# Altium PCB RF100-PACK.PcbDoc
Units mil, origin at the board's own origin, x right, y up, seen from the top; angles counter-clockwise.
Board outline 6000 x 4000 mil, 2 copper layers (Top Layer, Bottom Layer); 18 components, 15 nets, 75 pads, 285 vias.
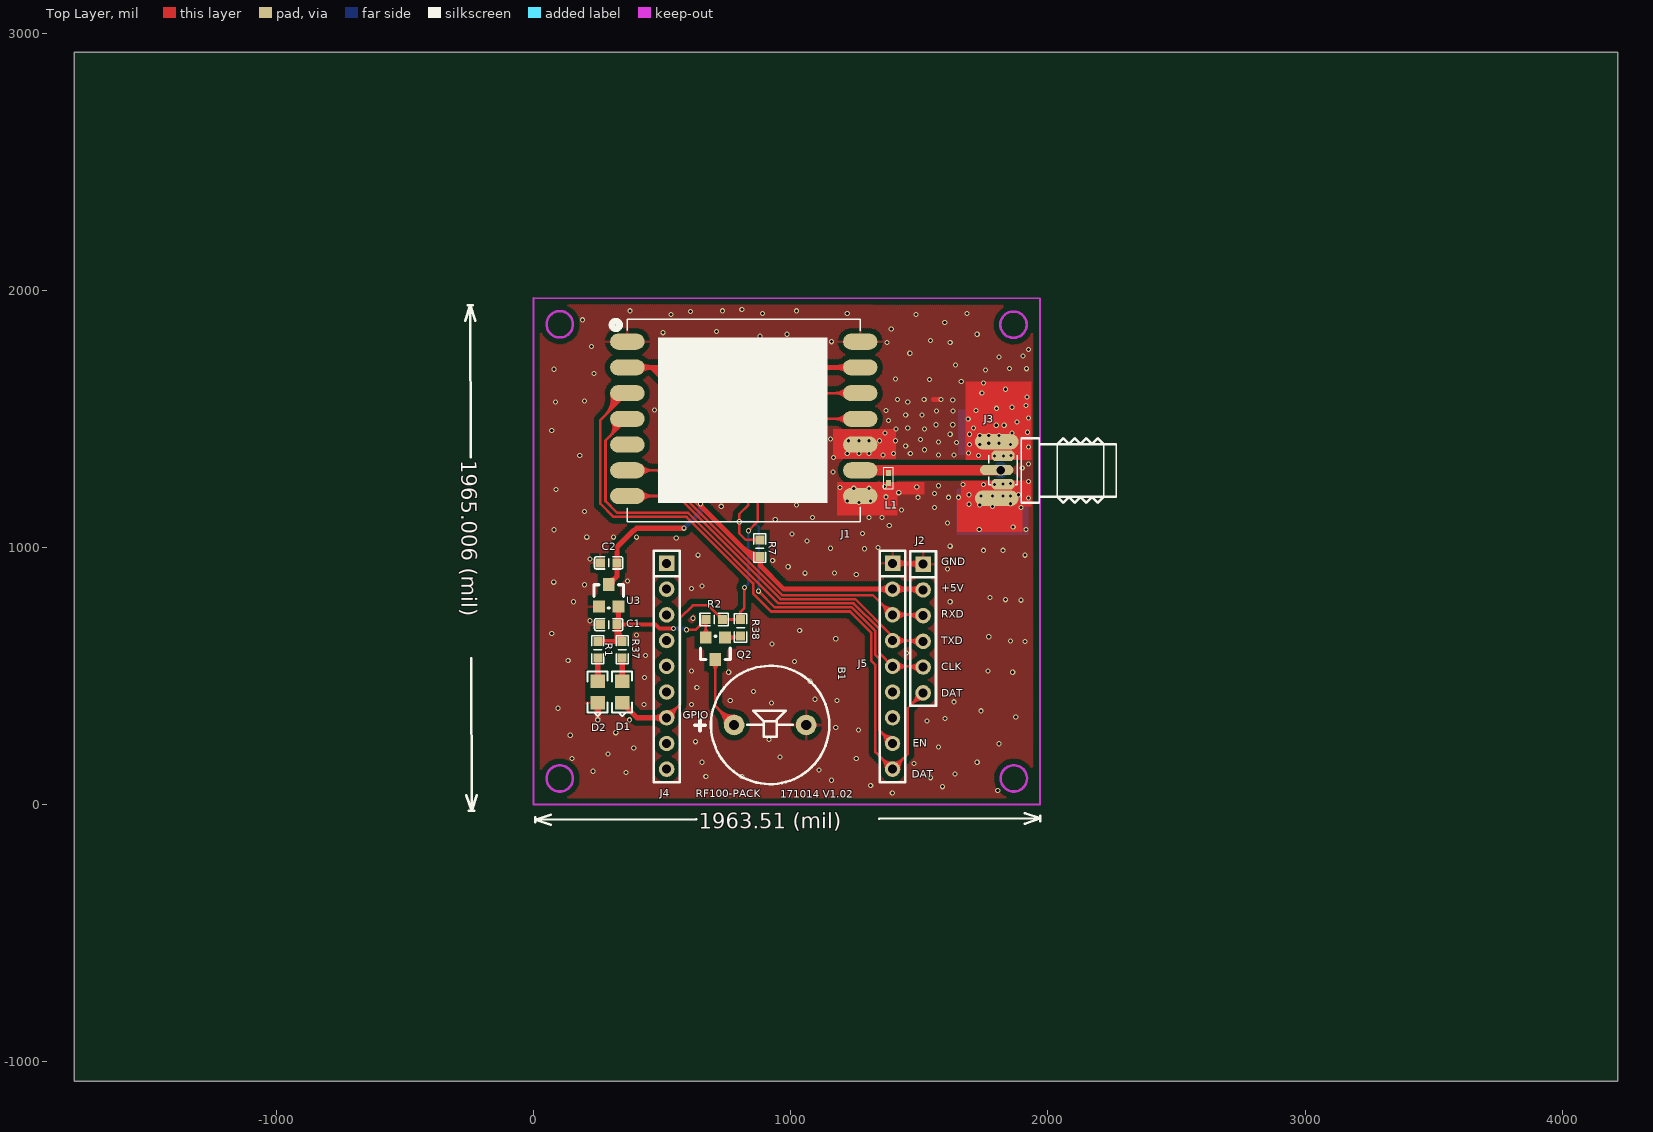
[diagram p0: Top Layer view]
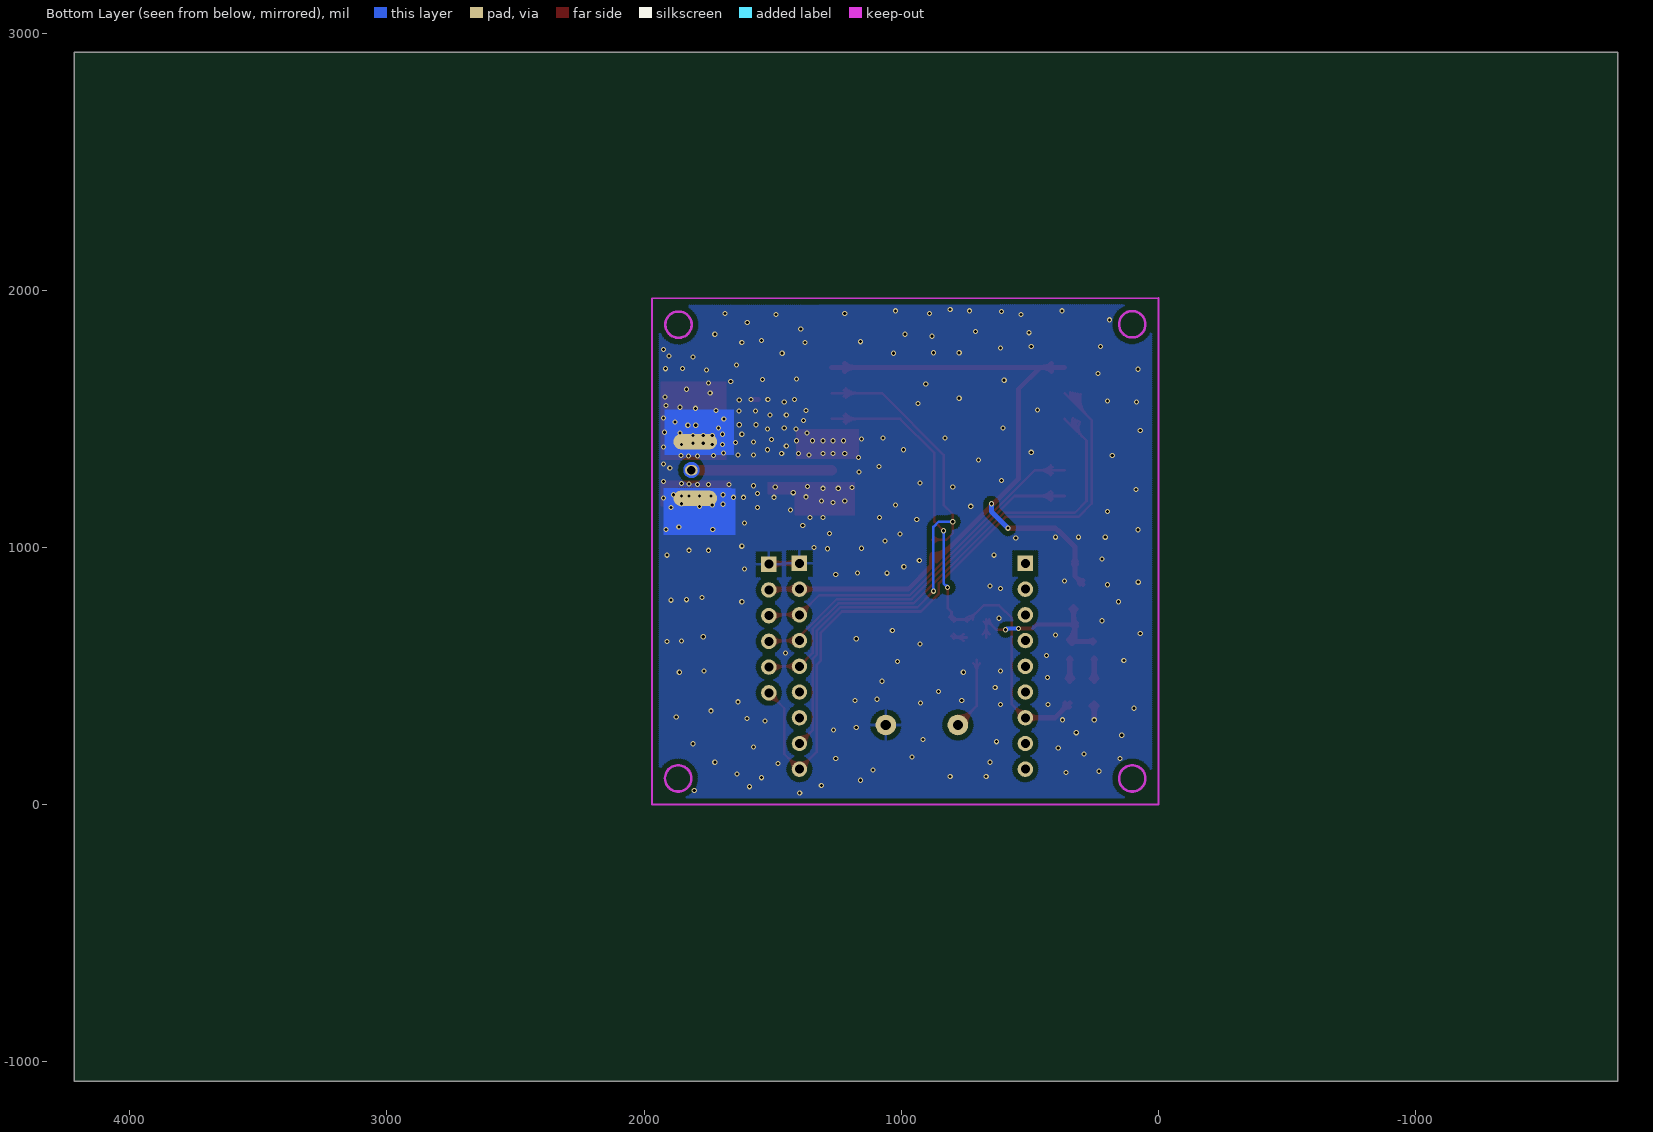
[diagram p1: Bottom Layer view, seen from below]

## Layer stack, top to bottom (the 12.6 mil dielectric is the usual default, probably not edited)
Top Layer: signal copper 1.4
Dielectric: dielectric 12.6, FR-4, Dk 4.8
Bottom Layer: signal copper 1.4

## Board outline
-1785,-1075 4215,-1075 4215,2925 -1785,2925

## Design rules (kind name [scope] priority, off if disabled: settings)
Clearance Clearance_component [(InPoly AND InLayerClass('Component Layers'))] p1: gap=20
Clearance Clearance_vcc [(InPoly AND OnLayer('VCC'))] p2: gap=10
Clearance Clearance_GND [(InPoly AND OnLayer('GND'))] p3: gap=10
Clearance Clearance_POLY [INPOLY] p4: gap=18
Clearance [All] p5: gap=6
ComponentClearance [All] p1 off: gap=10 collisioncheckmode=3 verticalgap=10 showdistances=FALSE
FabricationTestPointUsage TestPointUsage [All] p1: valid=0 allowmultiple=FALSE
FabricationTestpoint Testpoint [(IsPad And (OnTopLayer Or OnBottomLayer))] p1: side=3 testpointundercomponent=TRUE minsize=40 maxsize=100 preferedsize=60 minholesize=0 maxholesize=40 preferedholesize=32 testpointgrid=1 allowsidetop=TRUE allowsidebottom=TRUE usegrid=TRUE gridtolerance=0.01
HoleSize [All] p1: absolutevalues=TRUE maxlimit=300 minlimit=0 maxpercent=80.000 minpercent=20.000
HoleToHoleClearance [All] p1: gap=0 allowstackedmicrovias=TRUE
MinimumSolderMaskSliver [All] p1: minsoldermaskwidth=0
PolygonConnect PolygonConnect_1 [(InNet('GND'))] p1 off: connectstyle=Direct reliefconductorwidth=10 reliefentries=4 polygonreliefangle="90 Angle"
PolygonConnect PolygonConnect_via [(InPadClass('FREE'))  OR ISVIA] p2: connectstyle=Direct reliefconductorwidth=10 reliefentries=4 polygonreliefangle="90 Angle"
PolygonConnect [All] p3: connectstyle=Relief reliefconductorwidth=10 reliefentries=4 polygonreliefangle="90 Angle"
RoutingVias [All] p1: holewidth=12 width=20 viastyle="Through Hole" minholewidth=8 minwidth=8 maxholewidth=300 maxwidth=300
SilkToSilkClearance [All] p1: silktosilkclearance=0
SilkscreenOverComponentPads [All] p1: minsilkscreentomaskgap=0
SolderMaskExpansion [All] p1: expansion=4
Width [All] p1: maxlimit=80 minlimit=6 preferedwidth=7
20 further rules are at their usual default settings.

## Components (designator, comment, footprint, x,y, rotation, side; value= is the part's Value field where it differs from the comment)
B1 "BELL" BUZZ-.28/.46 780,310 r0 top
C1 "106" 0603C 325,700 r180 top
C2 "106" 0603C 325,940 r180 top
D1 "LED" LED-0805 345,480 r270 top
D2 "LED" LED-0805 250,480 r270 top
J1 "CON14" RF100 365,1100 r0 top
J2 "CON6" SIP-6 1515,935 r270 top
J3 "CON3" SMA 1815,1300 r270 top
J4 "CON9" SIP-9 518,938 r270 top
J5 "CON9" SIP-9 1396,938 r270 top
L1 "22nH" 0402R 1380,1290 r270 top
Q2 "S8550" SOT-23 745,650 r180 top
R1 "1K" 0603R 250,635 r270 top
R2 "10k" 0603R 670,720 r0 top
R7 "470k" 0603R 880,1030 r270 top
R37 "1k" 0603R 345,570 r90 top
R38 "3.3k" 0603R 805,655 r90 top
U3 "MD5333" SOT-23 255,770 r0 top

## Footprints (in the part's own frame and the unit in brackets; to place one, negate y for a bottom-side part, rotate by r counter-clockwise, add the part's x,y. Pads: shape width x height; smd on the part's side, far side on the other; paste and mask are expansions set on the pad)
0402R [mm]
  rect 0.6x0.5 smd: 1(0,0) 2(1.016,0)
  silkscreen extent -0.57,-0.46 1.59,0.46
0603C [mil]
  rect 35x35 smd: 1(0,0) 2(65,0)
  silkscreen extent -23,-24 88,24
0603R [mil]
  rect 35x35 smd: 1(0,0) 2(65,0)
  silkscreen extent -23,-24 88,24
BUZZ-.28/.46 [mil]
  round 80 hole 40: 1(0,0) 2(280,0)
  silkscreen extent -153,-230 370,230
LED-0805 [mil]
  rect 52x56 smd: 1(0,0) 2(84,0)
  silkscreen extent -38,-40 136,38
RF100 [mm]
  oval 3.4x1.6 smd: 1(0,17.78) 2(0,15.24) 3(0,12.7) 4(0,10.16) 5(0,7.62) 6(0,5.08) 7(0,2.54) 8(23,2.54) 9(23,5.08) 10(23,7.62) 11(23,10.16) 12(23,12.7) 13(23,15.24) 14(23,17.78)
  silkscreen extent -1.52,0 23,20
SIP-6 [mil]
  rect 60x60 hole 35: 1(0,0)
  round 60 hole 35: 2(100,0) 3(200,0) 4(300,0) 5(400,0) 6(500,0)
  silkscreen extent -50,-50 550,50
SIP-9 [mil]
  rect 60x60 hole 35: 1(0,0)
  round 60 hole 35: 2(100,0) 3(200,0) 4(300,0) 5(400,0) 6(500,0) 7(600,0) 8(700,0) 9(800,0)
  silkscreen extent -50,-50 850,50
SMA [mil]
  oval 60x170 smd: 1(-111.12,-13.75) 3(108.88,-13.75)
  oval 60x170 smd far side: 1(-111.12,-13.75) 3(108.88,-13.75)
  oct 40x90 smd: 1(-56.23,10.76) 3(53.77,10.76)
  oval 40x100 smd: 2(-1.23,-29.24)
  oval 40x120 smd: 2(-1.12,-8.75)
  oval 40x50 hole 32: 2(-0.52,1.17)
  Top Layer lines w17.7: -0.23,-9.75 -1.17,-8.8 -1.23,-8.75
  Bottom Layer circle w15.75: c-1.15,1.17 r23.62
  silkscreen extent -127,-44 129,451
SOT-23 [mil]
  rect 46x46 smd: 1(0,0) 2(75,0)
  rect 46x50 smd: 3(38,86)
  silkscreen extent -20,-5 95,85

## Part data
B1: "Bell"
C1 C2: library part CAP, "Capacitor"
J1 J2 J3 J4 J5: "Connector"
L1: library part INDUCTOR
Q2: library part PNP, "PNP Transistor"
R1 R2 R7 R37 R38: library part RES2
U3: library part SPX1117

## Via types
v1: diameter 20, hole 12, Top Layer to Bottom Layer, tented both sides, 279 vias
v2: diameter 20, hole 12, Top Layer to Bottom Layer, 6 vias

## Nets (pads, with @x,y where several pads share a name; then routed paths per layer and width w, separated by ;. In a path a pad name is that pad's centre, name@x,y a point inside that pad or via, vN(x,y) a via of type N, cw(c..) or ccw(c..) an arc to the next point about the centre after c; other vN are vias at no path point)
#RST: J1.5
+5V: C2.1 J1.2 J1.13 J2.2 J5.2 R7.2 U3.3 | length 4437
  Top Layer w20: U3.3 325,888 C2.1 ; 325,965 C2.1 ; J1.2 460,1700 ; v1(585,1075) 400,1075 391,1066 389.23,1066 325,1001.77 C2.1 ; R7.2@863.19,948.19 545,1266.39 545,1615 460,1700 ; R7.2 881.74,963.26 881.74,929.65 973.39,838 J5.2 1512,838 J2.2 ; 1183.15,1700 ccw(c1183.15,1751.93) J1.13@1219.87,1715.21 ; 1183.2,1700 cw(c1183.2,1648.14) J1.13@1219.87,1684.81 ; J1.13 460,1700 ; C2.1@319.7,945.3 ccw(c306.89,958.11) 325,958.11 ; C2.1@319.7,945.3 ccw(c306.89,958.11) 325,958.11 ; C2.1@319.7,945.3 ccw(c306.89,958.11) 325,958.11 ; C2.1@319.7,945.3 ccw(c306.89,958.11) 325,958.11 ; 325,921.89 cw(c343.11,921.89) 330.3,934.7 ccw(c343.11,921.89) 325,921.89 ; 325,921.89 ccw(c306.89,921.89) 319.7,934.7 cw(c306.89,921.89) 325,921.89 ; 325,958.11 ccw(c343.11,958.11) C2.1@330.3,945.3 ; 325,958.11 ccw(c343.11,958.11) C2.1@330.3,945.3 ; 325,958.11 ccw(c343.11,958.11) C2.1@330.3,945.3 ; 325,958.11 ccw(c343.11,958.11) C2.1@330.3,945.3 ; 452.33,1700 cw(c452.33,1751.9) 415.63,1715.2 ccw(c452.33,1751.9) 452.33,1700 ; 452.33,1700 ccw(c452.33,1648.1) 415.63,1684.8 cw(c452.33,1648.1) 452.33,1700 ; v1(650,1170) ccw(c670.79,1170) 656.09,1155.3 cw(c670.79,1170) v1(650,1170) ; v1(650,1170) cw(c650,1190.79) 635.3,1176.09 ccw(c650,1190.79) v1(650,1170) ; 1347.72,838 cw(c1347.72,789.72) 1381.86,823.86 ccw(c1347.72,789.72) 1347.72,838 ; 1347.72,838 ccw(c1347.72,886.28) 1381.86,852.14 cw(c1347.72,886.28) 1347.72,838 ; 1444.28,838 cw(c1444.28,886.28) 1410.14,852.14 ccw(c1444.28,886.28) 1444.28,838 ; 1444.28,838 ccw(c1444.28,789.72) 1410.14,823.86 cw(c1444.28,789.72) 1444.28,838 ; U3.3@293,871 ccw(c293,907.21) 318.61,881.61 cw(c293,907.21) U3.3@293,871 ; U3.3@306,858 cw(c332.56,858) 313.78,876.78 ccw(c332.56,858) U3.3@306,858 ; 809.82,1001.57 ccw(c880,1071.75) 880,972.5 cw(c880,1071.75) 809.82,1001.57 ; 843.96,967.43 ccw(c880,1003.47) 880,952.5 cw(c880,1003.47) 843.96,967.43 ; R7.2@874.7,959.7 cw(c857.69,942.69) 881.74,942.69 ccw(c857.69,942.69) R7.2@874.7,959.7 ; 1459.47,838 cw(c1459.47,779.47) 1500.86,820.86 ccw(c1459.47,779.47) 1459.47,838 ; 1473.96,838 ccw(c1473.96,876.04) 1500.86,849.14 cw(c1473.96,876.04) 1473.96,838
  Bottom Layer w20: v1(585,1075) 650,1140 v1(650,1170)
ANT: J1.9 J3.2 L1.1 | length 576.3
  Top Layer w40: J1.9 L1.1@1380,1300.01 ; 1408.59,1300.01 L1.1@1380,1300.01 ; J3.2@1806.25,1301.12 1805.13,1300.01 L1.1@1380,1300.01 ; L1.1@1372.82,1299.15 cw(c1374.89,1297.08) L1.1@1374.89,1300.01 ; L1.1@1372.82,1299.15 cw(c1374.89,1297.08) L1.1@1374.89,1300.01 ; L1.1@1372.82,1299.15 cw(c1374.89,1297.08) L1.1@1374.89,1300.01 ; L1.1@1385.11,1300.01 cw(c1385.11,1297.08) 1387.18,1299.15 ccw(c1385.11,1297.08) L1.1@1385.11,1300.01
BELL_EN: D1.2 J1.11 J4.7 R2.2 R38.2 | length 3445
  Top Layer w10: J4.7 570,390 570,725 620,775 680,775 R2.2 R38.2 805,750 ; v1(820,845) 820,765 805,750 ; v1(835.49,1065) 871.54,1101.05 871.54,1366.54 1005.01,1500.01 J1.11 ; 543.61,363.61 cw(c518,389.21) 518,353 ccw(c518,389.21) 543.61,363.61 ; 543.61,363.61 ccw(c569.21,338) 533,338 cw(c569.21,338) 543.61,363.61 ; 560.68,380.68 cw(c518,423.36) 518,363 ccw(c518,423.36) 560.68,380.68 ; 560.68,380.68 ccw(c603.36,338) 543,338 cw(c603.36,338) 560.68,380.68 ; 713.66,741.34 cw(c692.32,720) 722.5,720 ccw(c692.32,720) 713.66,741.34 ; 713.66,741.34 ccw(c735,762.68) 735,732.5 cw(c735,762.68) 713.66,741.34 ; 765.18,720 cw(c765.18,750.18) 743.84,728.84 ccw(c765.18,750.18) 765.18,720 ; 765.18,720 ccw(c765.18,689.82) 743.84,711.16 cw(c765.18,689.82) 765.18,720 ; 774.82,720 cw(c774.82,689.82) 796.16,711.16 ccw(c774.82,689.82) 774.82,720 ; 774.82,720 ccw(c774.82,750.18) 796.16,728.84 cw(c774.82,750.18) 774.82,720 ; 805,750 cw(c775.25,750) 796.2,728.88 ccw(c775.25,750) 805,750 ; 805,750 ccw(c834.75,750) 813.8,728.88 cw(c834.75,750) 805,750 ; 820,832.93 cw(c832.07,832.93) 823.54,841.46 ccw(c832.07,832.93) 820,832.93 ; 820,832.93 ccw(c807.93,832.93) 816.46,841.46 cw(c807.93,832.93) 820,832.93 ; 844.03,1073.54 cw(c835.49,1082.07) 835.49,1070 ccw(c835.49,1082.07) 844.03,1073.54 ; 844.03,1073.54 ccw(c852.56,1065) 840.49,1065 cw(c852.56,1065) 844.03,1073.54 ; 1171.1,1500.01 cw(c1171.1,1436.04) 1216.33,1481.27 ccw(c1171.1,1436.04) 1171.1,1500.01 ; 1171.1,1500.01 ccw(c1171.1,1563.98) 1216.33,1518.75 cw(c1171.1,1563.98) 1171.1,1500.01 ; 1195.24,1500.01 cw(c1195.24,1460.19) 1223.4,1488.35 ccw(c1195.24,1460.19) 1195.24,1500.01 ; 1195.24,1500.01 ccw(c1195.24,1539.83) 1223.4,1511.67 cw(c1195.24,1539.83) 1195.24,1500.01
  Top Layer w20: D1.2 403,338 J4.7 ; 469.72,338 cw(c469.72,289.72) 503.86,323.86 ccw(c469.72,289.72) 469.72,338 ; 469.72,338 ccw(c469.72,386.28) 503.86,352.14 cw(c469.72,386.28) 469.72,338 ; D1.2@347,380 cw(c347,346.2) 370.9,370.1 ccw(c347,346.2) D1.2@347,380 ; D1.2@363,396 ccw(c406.46,396) 375.73,365.27 cw(c406.46,396) D1.2@363,396
  Bottom Layer w10: v1(820,845) 835.49,860.49 v1(835.49,1065) ; 828.54,853.54 cw(c820,862.07) 820,850 ccw(c820,862.07) 828.54,853.54 ; 828.54,853.54 ccw(c837.07,845) 825,845 cw(c837.07,845) 828.54,853.54 ; 835.49,1052.93 cw(c847.56,1052.93) 839.03,1061.46 ccw(c847.56,1052.93) 835.49,1052.93 ; 835.49,1052.93 ccw(c823.42,1052.93) 831.95,1061.46 cw(c823.42,1052.93) 835.49,1052.93
EN: J1.12 J5.8 R7.1 | length 3179.6
  Top Layer w10: v1(875,830) 938,767 1237.75,767 1329,675.75 1329,582.37 1345,566.37 1345,289 J5.8 J5.8@1399,235 ; R7.1 825,1030 800,1055 v1(800,1100) 800,1129.51 835.24,1164.76 835.24,1360.24 1075.01,1600.01 J1.12 ; 800,1087.93 cw(c812.07,1087.93) 803.54,1096.46 ccw(c812.07,1087.93) 800,1087.93 ; 800,1087.93 ccw(c787.93,1087.93) 796.46,1096.46 cw(c787.93,1087.93) 800,1087.93 ; 800,1112.07 cw(c787.93,1112.07) 796.46,1103.54 ccw(c787.93,1112.07) 800,1112.07 ; 800,1112.07 ccw(c812.07,1112.07) 803.54,1103.54 cw(c812.07,1112.07) 800,1112.07 ; 849.82,1030 cw(c849.82,999.82) 871.16,1021.16 ccw(c849.82,999.82) 849.82,1030 ; 849.82,1030 ccw(c849.82,1060.18) 871.16,1038.84 cw(c849.82,1060.18) 849.82,1030 ; 883.54,821.46 cw(c892.07,830) 880,830 ccw(c892.07,830) 883.54,821.46 ; 883.54,821.46 ccw(c875,812.93) 875,825 cw(c875,812.93) 883.54,821.46 ; 1171.1,1600.01 cw(c1171.1,1536.04) 1216.33,1581.27 ccw(c1171.1,1536.04) 1171.1,1600.01 ; 1171.1,1600.01 ccw(c1171.1,1663.98) 1216.33,1618.75 cw(c1171.1,1663.98) 1171.1,1600.01 ; 1195.24,1600.01 cw(c1195.24,1560.19) 1223.4,1588.35 ccw(c1195.24,1560.19) 1195.24,1600.01 ; 1195.24,1600.01 ccw(c1195.24,1639.83) 1223.4,1611.67 cw(c1195.24,1639.83) 1195.24,1600.01 ; 1353.32,280.68 cw(c1310.64,238) 1371,238 ccw(c1310.64,238) 1353.32,280.68 ; 1353.32,280.68 ccw(c1396,323.36) 1396,263 cw(c1396,323.36) 1353.32,280.68 ; 1370.39,263.61 cw(c1344.79,238) 1381,238 ccw(c1344.79,238) 1370.39,263.61 ; 1370.39,263.61 ccw(c1396,289.21) 1396,253 cw(c1396,289.21) 1370.39,263.61
  Bottom Layer w10: v1(800,1100) 855,1100 875,1080 v1(875,830) ; 812.07,1100 cw(c812.07,1112.07) 803.54,1103.54 ccw(c812.07,1112.07) 812.07,1100 ; 812.07,1100 ccw(c812.07,1087.93) 803.54,1096.46 cw(c812.07,1087.93) 812.07,1100 ; 875,842.07 cw(c862.93,842.07) 871.46,833.54 ccw(c862.93,842.07) 875,842.07 ; 875,842.07 ccw(c887.07,842.07) 878.54,833.54 cw(c887.07,842.07) 875,842.07
GND: B1.2 C1.2 C2.2 D2.2 J1.1 J1.8 J1.10 J1.14 J2.1 J3.1 J3.3 J5.1 L1.2 U3.1 | length 630.8
  Top Layer w20: v1(250,330) D2.2 ; J5.1 1512,938 J2.1 ; 1555,1575 1574.81,1575 ; 250,357.37 cw(c288.63,357.37) 261.31,384.69 ccw(c288.63,357.37) 250,357.37 ; 250,357.37 ccw(c211.37,357.37) 238.69,384.69 cw(c211.37,357.37) 250,357.37 ; 1444.28,938 cw(c1444.28,986.28) 1410.14,952.14 ccw(c1444.28,986.28) 1444.28,938 ; 1444.28,938 ccw(c1444.28,889.72) 1410.14,923.86 cw(c1444.28,889.72) 1444.28,938 ; 1459.47,938 cw(c1459.47,879.47) 1500.86,920.86 ccw(c1459.47,879.47) 1459.47,938 ; 1473.96,938 ccw(c1473.96,976.04) 1500.86,949.14 cw(c1473.96,976.04) 1473.96,938
  other v1: 1395,45 1805,55 1590,70 1311,75 1159,95 1543,105 810,109 670,110 1639,120 360,125 231,130 1110,135 1479,160 655,165 1725,165 150,180 1255,180 959,185 290,197 390,221 1575,225 1810,237 630,245 915,253 143,270 320,280 1263,290 1175,300 1530,325 373,330 1600,335 1875,341 1740,365 95,375 430,389 615,390 925,395 1635,400 765,405 1180,405 1095,410 855,440 635,455 1075,480 431,495 759,515 1863,515 615,520 1767,520 1015,557 135,560 435,580 1450,590 927,625 1911,635 1855,637 1175,645 1770,653 400,660 71,665 1035,677 220,715 620,725 155,789 1620,789 1895,795 1835,797 1775,805 615,840 655,850 199,855 79,865 365,870 1255,895 1055,900 1170,901 1610,917 990.23,925 930,949 220,955 639,970 1911,970 1750,989 1825,989 1287,995 1155,997 1340,1000 1620,1005 1063,1025 555,1037 207,1040 311,1040 400,1040 1005,1053 1279,1055 80,1069 1733,1070 1915,1070 1865,1080 1383,1085 1610,1095 940,1109 1085,1117 1305,1117 1355,1117 199,1140 1431,1145 1559,1155 1895,1155 730,1160 1785,1160 1023,1165 1735,1165 1693,1168 1855,1170 1265,1175 1220,1180 1310,1180 1925,1192 1495,1195 1613,1195 1653,1195 1370,1197 1740,1200 1785,1200 1825,1200 1855,1200 1693,1205 1885,1205 1559,1210 1420,1213 87,1225 1245,1230 1305,1230 1191,1233.74 800,1235 1490,1235 1365,1237 1575,1240 1670,1245 1749,1245 927,1250 1925,1256 610,1260 1165,1293 1900,1309 1087,1315 1925,1325 700,1340 1167,1350 180,1357 1730,1357 1359,1360 1575,1360 1635,1360 1220,1365 1265,1365 1305,1365 1399,1365 1465,1365 1691.25,1367.12 495,1370 991,1380 1520,1380 1925,1390 1447,1395 1695,1400 1735,1400 1855,1400 1770,1405 1810,1405 1645,1408 1575,1410 1225,1415 1265,1415 1305,1415 1345,1415 1407,1415 1505,1420 1155,1421 830,1425 1071,1425 1735,1435 1770,1435 1810,1435 1620,1440 1695,1440 1367,1445 1860,1445 1920,1448 71,1455 1410,1461 1520,1461 605,1465 1455,1465 1711,1465 1799,1475 1830,1475 1565,1477 1630,1477 1880,1488 1380,1493 1690,1500 1925,1504 1447,1515 1511,1515 1567,1530 1631,1530 1370,1533 1720,1533 470,1535 1800,1541 1861,1545 1915,1552 935,1560 85,1565 1455,1565 199,1570 1630,1573 1415,1575 1519,1575 1585,1575 775,1580 1919,1585 1743,1600 1835,1615 905,1635 1750,1640 1663,1645 600,1650 1540,1653 1407,1655 235,1677 1757,1690 80,1693 1917,1695 1850,1696 1640,1710 1810,1741 1903,1745 1031,1755 1463,1755 775,1757 875,1757 1925,1770 615,1775 225,1781 495,1781 1375,1797 1620,1797 1159,1800 1543,1805 880,1821 985,1829 1725,1829 503,1835 711,1840 1391,1850 1599,1875 190,1885 535,1905 1487,1905 890,1909 1220,1909 1685,1909 610,1917 375,1920 735,1920 1023,1920 810,1925
  other v2: 1792.75,1244.23 1824.75,1246.23 1854.76,1248.15 1792.75,1355.23 1826.76,1355.23 1856.75,1357.23
ICE_CLK: J1.4 J2.5 J5.5 | length 2889.6
  Top Layer w10: J1.4 280,1415 280,1180 325,1135 601.44,1135 953.44,783 1244.37,783 1345,682.37 1345,589 J5.5 1512,538 J2.5 ; 1432.21,538 cw(c1432.21,574.21) 1406.61,548.61 ccw(c1432.21,574.21) 1432.21,538 ; 1432.21,538 ccw(c1432.21,501.79) 1406.61,527.39 cw(c1432.21,501.79) 1432.21,538 ; 1456.36,538 cw(c1456.36,598.36) 1413.68,555.68 ccw(c1456.36,598.36) 1456.36,538 ; 1456.36,538 ccw(c1456.36,477.64) 1413.68,520.32 cw(c1456.36,477.64) 1456.36,538 ; 297.72,1432.72 ccw(c264.53,1465.91) 306.1,1487.7 cw(c264.53,1465.91) 297.72,1432.72 ; 307.33,1442.33 ccw(c277.15,1472.52) 314.96,1492.34 cw(c277.15,1472.52) 307.33,1442.33 ; 316.95,1451.95 ccw(c289.76,1479.13) 323.81,1496.98 cw(c289.76,1479.13) 316.95,1451.95 ; 326.56,1461.56 ccw(c302.38,1485.75) 332.67,1501.63 cw(c302.38,1485.75) 326.56,1461.56 ; 1447.4,538 cw(c1447.4,467.4) 1497.32,517.32 ccw(c1447.4,467.4) 1447.4,538 ; 1461.89,538 ccw(c1461.89,588.11) 1497.32,552.68 cw(c1461.89,588.11) 1461.89,538 ; 1471.54,538 cw(c1471.54,491.54) 1504.39,524.39 ccw(c1471.54,491.54) 1471.54,538
ICE_DAT: J1.3 J2.6 J5.9 | length 4222.6
  Top Layer w10: J1.3 260,1495 260,1170 311,1119 594.81,1119 854,859.81 854,821.3 924.3,751 1231.12,751 1313,669.12 1313,559.75 1329,543.75 1329,205 J5.9 1455,197 1455,375 J2.6 ; 1353.32,180.68 cw(c1310.64,138) 1371,138 ccw(c1310.64,138) 1353.32,180.68 ; 1353.32,180.68 ccw(c1396,223.36) J5.9@1396,163 ; 1353.32,180.68 ccw(c1396,223.36) J5.9@1396,163 ; 1370.39,163.61 cw(c1344.79,138) 1381,138 ccw(c1344.79,138) 1370.39,163.61 ; 1370.39,163.61 ccw(c1396,189.21) J5.9@1396,153 ; 1370.39,163.61 ccw(c1396,189.21) J5.9@1396,153 ; J5.9@1396,153 ccw(c1396,189.21) 1421.61,163.61 ; J5.9@1396,153 ccw(c1396,189.21) 1421.61,163.61 ; J5.9@1396,163 ccw(c1396,223.36) 1438.68,180.68 ; J5.9@1396,163 ccw(c1396,223.36) 1438.68,180.68 ; 1421.61,163.61 ccw(c1447.21,138) 1411,138 cw(c1447.21,138) 1421.61,163.61 ; 1438.68,180.68 ccw(c1481.36,138) 1421,138 cw(c1481.36,138) 1438.68,180.68 ; 1472.32,392.32 cw(c1515,349.64) 1515,410 ccw(c1515,349.64) 1472.32,392.32 ; 1472.32,392.32 ccw(c1429.64,435) 1490,435 cw(c1429.64,435) 1472.32,392.32 ; 1489.39,409.39 cw(c1515,383.79) 1515,420 ccw(c1515,383.79) 1489.39,409.39 ; 1489.39,409.39 ccw(c1463.79,435) 1500,435 cw(c1463.79,435) 1489.39,409.39 ; 277.72,1512.72 ccw(c211.85,1578.59) 303.5,1595.26 cw(c211.85,1578.59) 277.72,1512.72 ; 291.21,1526.21 ccw(c234.69,1582.74) 313.34,1597.05 cw(c234.69,1582.74) 291.21,1526.21 ; 304.71,1539.71 ccw(c257.52,1586.89) 323.18,1598.84 cw(c257.52,1586.89) 304.71,1539.71 ; 318.2,1553.2 ccw(c280.36,1591.05) 333.01,1600.63 cw(c280.36,1591.05) 318.2,1553.2 ; 331.7,1566.7 ccw(c303.19,1595.2) 342.85,1602.42 cw(c303.19,1595.2) 331.7,1566.7
NetB1_1: B1.1 Q2.3 | length 875.8
  Top Layer w10: Q2.3 707,383 B1.1 ; 707,518.54 cw(c750.46,518.54) 719.73,549.27 ccw(c750.46,518.54) 707,518.54 ; 707,518.54 ccw(c663.54,518.54) 694.27,549.27 cw(c663.54,518.54) 707,518.54 ; 720.25,369.75 cw(c660.5,310) 745,310 ccw(c660.5,310) 720.25,369.75 ; 720.25,369.75 ccw(c780,429.5) 780,345 cw(c780,429.5) 720.25,369.75 ; 737.32,352.68 cw(c694.64,310) 755,310 ccw(c694.64,310) 737.32,352.68 ; 737.32,352.68 ccw(c780,395.36) 780,335 cw(c780,395.36) 737.32,352.68
NetD1_1: D1.1 R37.1 | length 268.2
  Top Layer w20: D1.1 R37.1 ; 345,518.63 cw(c306.37,518.63) 333.69,491.31 ccw(c306.37,518.63) 345,518.63 ; 345,518.63 ccw(c383.63,518.63) 356.31,491.31 cw(c383.63,518.63) 345,518.63 ; 345,551.89 cw(c363.11,551.89) 350.3,564.7 ccw(c363.11,551.89) 345,551.89 ; 345,551.89 ccw(c326.89,551.89) 339.7,564.7 cw(c326.89,551.89) 345,551.89
NetD2_1: D2.1 R1.2 | length 268.2
  Top Layer w20: D2.1 R1.2 ; 250,518.63 cw(c211.37,518.63) 238.69,491.31 ccw(c211.37,518.63) 250,518.63 ; 250,518.63 ccw(c288.63,518.63) 261.31,491.31 cw(c288.63,518.63) 250,518.63 ; 250,551.89 cw(c268.11,551.89) 255.3,564.7 ccw(c268.11,551.89) 250,551.89 ; 250,551.89 ccw(c231.89,551.89) 244.7,564.7 cw(c231.89,551.89) 250,551.89
NetQ2_1: Q2.1 R38.1 | length 329.7
  Top Layer w10: Q2.1 800,650 R38.1 ; 786.89,650 cw(c786.89,636.89) 796.16,646.16 ccw(c786.89,636.89) 786.89,650 ; 786.89,650 ccw(c786.89,673.11) 803.23,656.77 cw(c786.89,673.11) 786.89,650 ; R38.1@788.46,650 cw(c788.46,693.46) 757.73,662.73 ccw(c788.46,693.46) R38.1@788.46,650 ; R38.1@788.46,650 ccw(c788.46,606.54) 757.73,637.27 cw(c788.46,606.54) R38.1@788.46,650 ; Q2.1@762.75,650 ccw(c762.75,697.25) 796.16,663.84 cw(c762.75,697.25) Q2.1@762.75,650
RXD: J1.6 J2.3 J5.3 | length 2589.8
  Top Layer w10: J1.6 481.69,1300 966.69,815 1319,815 J5.3 1398,740 J2.3@1515,740 ; 440.26,1300 cw(c440.26,1339.82) 412.1,1311.66 ccw(c440.26,1339.82) 440.26,1300 ; 440.26,1300 ccw(c440.26,1260.18) 412.1,1288.34 cw(c440.26,1260.18) 440.26,1300 ; 464.4,1300 cw(c464.4,1363.97) 419.17,1318.74 ccw(c464.4,1363.97) 464.4,1300 ; 464.4,1300 ccw(c464.4,1236.03) 419.17,1281.26 cw(c464.4,1236.03) 464.4,1300 ; 1353.32,780.68 cw(c1310.64,738) 1371,738 ccw(c1310.64,738) 1353.32,780.68 ; 1353.32,780.68 ccw(c1396,823.36) 1396,763 cw(c1396,823.36) 1353.32,780.68 ; 1370.39,763.61 cw(c1344.79,738) 1381,738 ccw(c1344.79,738) 1370.39,763.61 ; 1370.39,763.61 ccw(c1396,789.21) 1396,753 cw(c1396,789.21) 1370.39,763.61 ; 1466.72,740 cw(c1466.72,686.72) 1504.39,724.39 ccw(c1466.72,686.72) 1466.72,740 ; 1466.72,740 ccw(c1466.72,783.28) 1497.32,752.68 cw(c1466.72,783.28) 1466.72,740 ; J5.3@1406.61,727.39 cw(c1437.04,696.96) 1437.04,740 ccw(c1437.04,696.96) J5.3@1406.61,727.39 ; J5.3@1406.61,748.61 ccw(c1427.38,769.38) 1427.38,740 cw(c1427.38,769.38) J5.3@1406.61,748.61 ; J5.3@1413.68,720.32 cw(c1461.18,672.82) 1461.18,740 ccw(c1461.18,672.82) J5.3@1413.68,720.32 ; J5.3@1413.68,755.68 ccw(c1451.53,793.53) 1451.53,740 cw(c1451.53,793.53) J5.3@1413.68,755.68 ; 1442.57,740 cw(c1442.57,662.57) 1497.32,717.32 ccw(c1442.57,662.57) 1442.57,740
TXD: J1.7 J2.4 J5.4 | length 2289
  Top Layer w10: J1.7@366,1199 J1.7 559.06,1200 960.06,799 1251,799 1396,654 J5.4 ; J5.4@1400.83,640 ccw(c1400.83,633.17) J5.4 ; J2.4@1513,638 J5.4 ; 440.26,1200 cw(c440.26,1239.82) 412.1,1211.66 ccw(c440.26,1239.82) 440.26,1200 ; 440.26,1200 ccw(c440.26,1160.18) 412.1,1188.34 cw(c440.26,1160.18) 440.26,1200 ; 464.4,1200 cw(c464.4,1263.97) 419.17,1218.74 ccw(c464.4,1263.97) 464.4,1200 ; 464.4,1200 ccw(c464.4,1136.03) 419.17,1181.26 cw(c464.4,1136.03) 464.4,1200 ; 1432.21,638 cw(c1432.21,674.21) 1406.61,648.61 ccw(c1432.21,674.21) 1432.21,638 ; 1432.21,638 ccw(c1432.21,601.79) 1406.61,627.39 cw(c1432.21,601.79) 1432.21,638 ; 1456.36,638 cw(c1456.36,698.36) 1413.68,655.68 ccw(c1456.36,698.36) 1456.36,638 ; 1456.36,638 ccw(c1456.36,577.64) 1413.68,620.32 cw(c1456.36,577.64) 1456.36,638 ; 1447.4,638 cw(c1447.4,567.4) 1497.32,617.32 ccw(c1447.4,567.4) 1447.4,638 ; 1461.89,638 ccw(c1461.89,688.11) 1497.32,652.68 cw(c1461.89,688.11) 1461.89,638 ; 1471.54,638 cw(c1471.54,591.54) 1504.39,624.39 ccw(c1471.54,591.54) 1471.54,638
VCC_3V3: C1.1 Q2.2 R1.1 R2.1 R37.2 U3.2 | length 1730.3
  Top Layer w10: v1(595,680) 630,680 R2.1 Q2.2 ; 607.07,680 cw(c607.07,692.07) 598.54,683.54 ccw(c607.07,692.07) 607.07,680 ; 607.07,680 ccw(c607.07,667.93) 598.54,676.46 cw(c607.07,667.93) 607.07,680 ; 648.66,698.66 cw(c670,677.32) 670,707.5 ccw(c670,677.32) 648.66,698.66 ; 648.66,698.66 ccw(c627.32,720) 657.5,720 cw(c627.32,720) 648.66,698.66 ; 670,689.82 cw(c700.18,689.82) 678.84,711.16 ccw(c700.18,689.82) 670,689.82 ; 670,689.82 ccw(c639.82,689.82) 661.16,711.16 cw(c639.82,689.82) 670,689.82 ; 670,693.46 cw(c626.54,693.46) 657.27,662.73 ccw(c626.54,693.46) 670,693.46 ; 670,693.46 ccw(c713.46,693.46) 682.73,662.73 cw(c713.46,693.46) 670,693.46
  Top Layer w15: C1.1 475,700 490,685 v1(545,685) ; 349.14,700 cw(c349.14,724.14) 332.07,707.07 ccw(c349.14,724.14) 349.14,700 ; 349.14,700 ccw(c349.14,675.86) 332.07,692.93 cw(c349.14,675.86) 349.14,700
  Top Layer w20: R1.1 R37.2 325,655 C1.1 ; U3.2 330,705 C1.1 ; 268.11,635 cw(c268.11,653.11) 255.3,640.3 ccw(c268.11,653.11) 268.11,635 ; 268.11,635 ccw(c268.11,616.89) 255.3,629.7 cw(c268.11,616.89) 268.11,635 ; 325,681.89 cw(c343.11,681.89) 330.3,694.7 ccw(c343.11,681.89) 325,681.89 ; 325,681.89 ccw(c306.89,681.89) 319.7,694.7 cw(c306.89,681.89) 325,681.89 ; C1.1 ccw(c408.06,700) 350.22,640.38 cw(c408.06,700) C1.1 ; 326.89,635 cw(c326.89,616.89) 339.7,629.7 ccw(c326.89,616.89) 326.89,635 ; 326.89,635 ccw(c326.89,653.11) 339.7,640.3 cw(c326.89,653.11) 326.89,635 ; 330,738.62 cw(c361.38,738.62) 339.19,760.81 ccw(c361.38,738.62) 330,738.62 ; 330,738.62 ccw(c298.62,738.62) 320.81,760.81 cw(c298.62,738.62) 330,738.62 ; R37.2@332.2,647.8 cw(c319.39,635) 337.5,635 ccw(c319.39,635) R37.2@332.2,647.8 ; R37.2@332.2,647.8 ccw(c345,660.61) 345,642.5 cw(c345,660.61) R37.2@332.2,647.8 ; C1.1@319.7,705.3 ccw(c294.82,730.18) 330,730.18 cw(c294.82,730.18) C1.1@319.7,705.3 ; 325,652.73 ccw(c362.2,652.73) 336.3,626.03 cw(c362.2,652.73) 325,652.73
  Bottom Layer w15: v1(545,685) 590,685 v1(595,680) ; 576.89,685 cw(c576.89,661.89) 593.23,678.23 ccw(c576.89,661.89) 576.89,685
pads on no net: J4.1 J4.2 J4.3 J4.4 J4.5 J4.6 J4.8 J4.9 J5.6 J5.7

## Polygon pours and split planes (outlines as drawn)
GND on Top Layer "top" (hatched 90Degree grid 8 track 8, remove dead copper, pour order 1000): -5,1963.99 1969.24,1963.99 1969.24,-1.01 -5,-1.01 -5,1963.99
GND on Bottom Layer "top" (hatched 90Degree grid 8 track 8, remove dead copper, pour order 1001): 0,1960 1969.25,1960 1969.25,0 0,0 0,1960

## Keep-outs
Keep-Out Layer:
  circle w10: c102.36,1867.64 r51.18
  circle w10: c1866.14,1866.14 r51.18
  circle w10: c1867.64,102.36 r51.18
  circle w10: c102.36,102.36 r51.18
  lines w8: 0,0 240,0 1968.5,0 1968.5,1968.5 0,1970 0,0

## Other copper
Top Layer:
  region net GND: 1647,1205 1647,1060 1901,1060 1901,1205
  region net GND: 1679,1645 1679,1340 1937,1340 1937,1645
  region net GND: 1662,1260 1662,1160 1937,1160 1937,1260
  region net GND: 1520,1205 1520,1255 1404.16,1255 1404.16,1205
  rectangle net GND: 1180,1125 1415,1255
  rectangle net GND: 1165,1344.01 1408.59,1461
Bottom Layer:
  region net GND: 1645,1230 1645,1048 1925,1048 1925,1230
  region net GND: 1650,1536 1650,1360 1920,1360 1920,1536
  region net GND: 1660,1232 1660,1160 1925,1160 1925,1232

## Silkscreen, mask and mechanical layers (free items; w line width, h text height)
Top Overlay:
  lines w10: -265.46,1881.65 -245.62,1941.7 ; -260.77,36.65 -240.62,-23.3 ; -255.62,1941.68 -235.62,1941.73 ; -250.62,-23.32 -230.62,-23.27 ; -244.11,1350.08 -245.62,1941.7 ; -242.12,568.33 -240.62,-23.3 ; -225.46,1881.76 -245.62,1941.7 ; -220.77,36.76 -240.62,-23.3 ; 7.34,-48.44 7.39,-68.44 ; 67.31,-38.29 7.36,-58.44 ; 67.41,-78.29 7.36,-58.44 ; 633.23,-56.85 7.36,-58.44 ; 1345,-55.04 1970.87,-53.44 ; 1910.82,-33.6 1970.87,-53.44 ; 1910.92,-73.6 1970.87,-53.44 ; 1970.84,-43.44 1970.89,-63.44
  text "1965.006 (mil)" at -280.08,1339.99 h60 r270.15
  text "GND" at 1585,930 h30
  text "+5V" at 1585,828 h30
  text "RXD" at 1585,726 h30
  text "TXD" at 1585,624 h30
  text "CLK" at 1585,522 h30
  text "DAT" at 1585,420 h30
  text "GPIO" at 580,335 h30
  text "EN" at 1475,225 h30
  text "DAT" at 1470,105 h30
  text "RF100-PACK" at 630,29 h30
  text "171014 V1.02" at 959,28 h30
  text "1963.51 (mil)" at 643.32,-92.82 h60 r0.15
